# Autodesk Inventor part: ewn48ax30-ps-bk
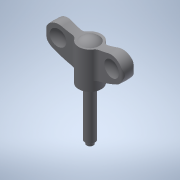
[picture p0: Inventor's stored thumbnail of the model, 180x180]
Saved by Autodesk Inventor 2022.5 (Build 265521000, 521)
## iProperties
Created: 2016-12
Part Number: ewn48ax30-ps-bk
Material: 一般
Document SubType Name: Modeling
Designer: imaocorp
Density: 1 g/cm^3
Appearance: 既定
Author: imaocorp
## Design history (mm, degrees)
node "ewn48ax30-ps-bk.x_t1"
node "ewn48ax30-ps-bk"
node "Base1"
